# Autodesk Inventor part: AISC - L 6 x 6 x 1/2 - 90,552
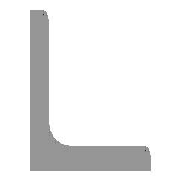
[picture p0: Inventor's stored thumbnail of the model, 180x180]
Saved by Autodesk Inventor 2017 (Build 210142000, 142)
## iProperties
Created: 2016-02
Part Number: AISC - L 6 x 6 x 1/2 - 90,552
Material: Stal, miękka
Description: Kątownik
Document SubType Name: Modeling
Standard: ANSI
Designer: X
Standards Organization: ANSI
Language: pl-PL
Size Designation: L 6 x 6 x 1/2
Categories: <MemberInstance><Categories><Category DisplayName="Kształtowniki konstrukcyjne" InternalName="089c4875-fa83-4c05-b084-43b9cc11f5ed" Mnemonic="GRDR"><CategoryPar
Stock Number: L 6 x 6 x 1/2
Density: 7.85 g/cm^3
Appearance: Częściowo polerowana
IsCustomPart: 1
G_L: 2300,022 mm
G_W: 152,400 mm
G_H: 152,400 mm
_CCFamilyMember: 47
_CCFamilyDisplayName: ANSI L (Kątownik równoramienny) - Kątownik — Rozmiary w nawiasach zostały wycofane
_FrameMemberDoc: Frame Member File
_Version: 15.0.0
_GetPNFromCC: 1
Author: X
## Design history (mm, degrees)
node "Płaszczyzna początkowa"
node "Płaszczyzna końcowa"
sketch "Szkic"
  geometry: L1 (152.4, 0)-(0, 0); L2 (0, 0)-(0, 152.4); L3 (0, 152.4)-(6.35, 152.4); L4 (12.7, 146.05)-(12.7, 25.4); L5 (25.4, 12.7)-(146.05, 12.7); L6 (152.4, 6.35)-(152.4, 0); L7 (0, -11.041)-(0, 31.538); L8 (-11.041, 0)-(31.538, 0); L9 (0, 186.666)-(0, -43.993) reference; L10 (-43.993, 0)-(186.666, 0) reference; A1 r 12.7 centre (25.4, 25.4) between (12.7, 25.4) and (25.4, 12.7); A2 r 6.35 centre (6.35, 146.05) between (12.7, 146.05) and (6.35, 152.4); A3 r 6.35 centre (146.05, 6.35) between (152.4, 6.35) and (146.05, 12.7); 3 further points
  constraints: 16 end point, 6 point on circle, 6 point on line, 6 tangent, 4 parallel, 3 centre point, 2 collinear, 1 equal radius, 1 horizontal, 1 perpendicular
  dimensions: "d0" = 152.4 distance between parallel lines of L6 L2 (= G_H); "d1" = 152.4 distance between parallel lines of L3 L1 (= G_H); "d2" = 12.7 distance between parallel lines of L2 L4 (= G_T); "d3" = 12.7 distance between parallel lines of L1 L5 (= G_T); "d10" = 0 distance between parallel lines of L7 L2 (computed from ex); "d11" = 0 distance between parallel lines of L8 L1 (computed from d10); "d14" = 12.7 radius of A1 (= G_IR); "d15" = 6.35 radius of A2 (= G_ER)
extrude "Bryła" new body sketch "Szkic" stored distance "d4" = 2300.02174 (= G_L); taper "d5" = 0 deg
node "Driven Length"
  sketch "Sketch3"
    geometry: L1 (0, 0)-(10, 0) reference
    constraints: 2 end point, 1 horizontal
  workplane "Work Plane3"
  sketch "Sketch4"
    geometry: L1 (-2, 0)-(12, 0) reference; L2 (-2, 2300.022)-(12, 2300.022) reference
    dimensions: "d17" = 2300.02174 distance between parallel lines of L1 L2 (derived)
body "Solid1"
other parameters: "G_H" = 152.4 [user parameter; used in 2 equation terms], "G_T" = 12.7 [user parameter; used in 2 equation terms], "G_ER" = 6.35 [user parameter; used in 1 equation term], "G_IR" = 12.7 [user parameter; used in 1 equation term], "G_L" = 2300.02174 (= d17) [user parameter; used in 1 equation term], "ex" = 0 [user parameter; used in 1 equation term], "G_OFFSET_START" = 0 [user parameter; used in 1 equation term], "G_OFFSET_END" = 0 [user parameter; used in 1 equation term], "d12" = 0 (computed from G_OFFSET_START), "d13" = 2300.02174 (= G_OFFSET_END + B_L), "B_L" = 2300.02174 [user parameter; used in 1 equation term], "d16" = 90 deg, "MAS" = 2.9168 [user parameter]
